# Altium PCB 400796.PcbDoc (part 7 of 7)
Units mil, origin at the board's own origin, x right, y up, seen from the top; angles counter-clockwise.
Board outline 2086.61 x 2086.61 mil, 6 copper layers (Top Layer, Mid Layer 1, Mid Layer 2, Mid Layer 3, Mid Layer 4, Bottom Layer), stack 58.818 mil thick; 313 components, 234 nets, 1244 pads, 2538 vias.
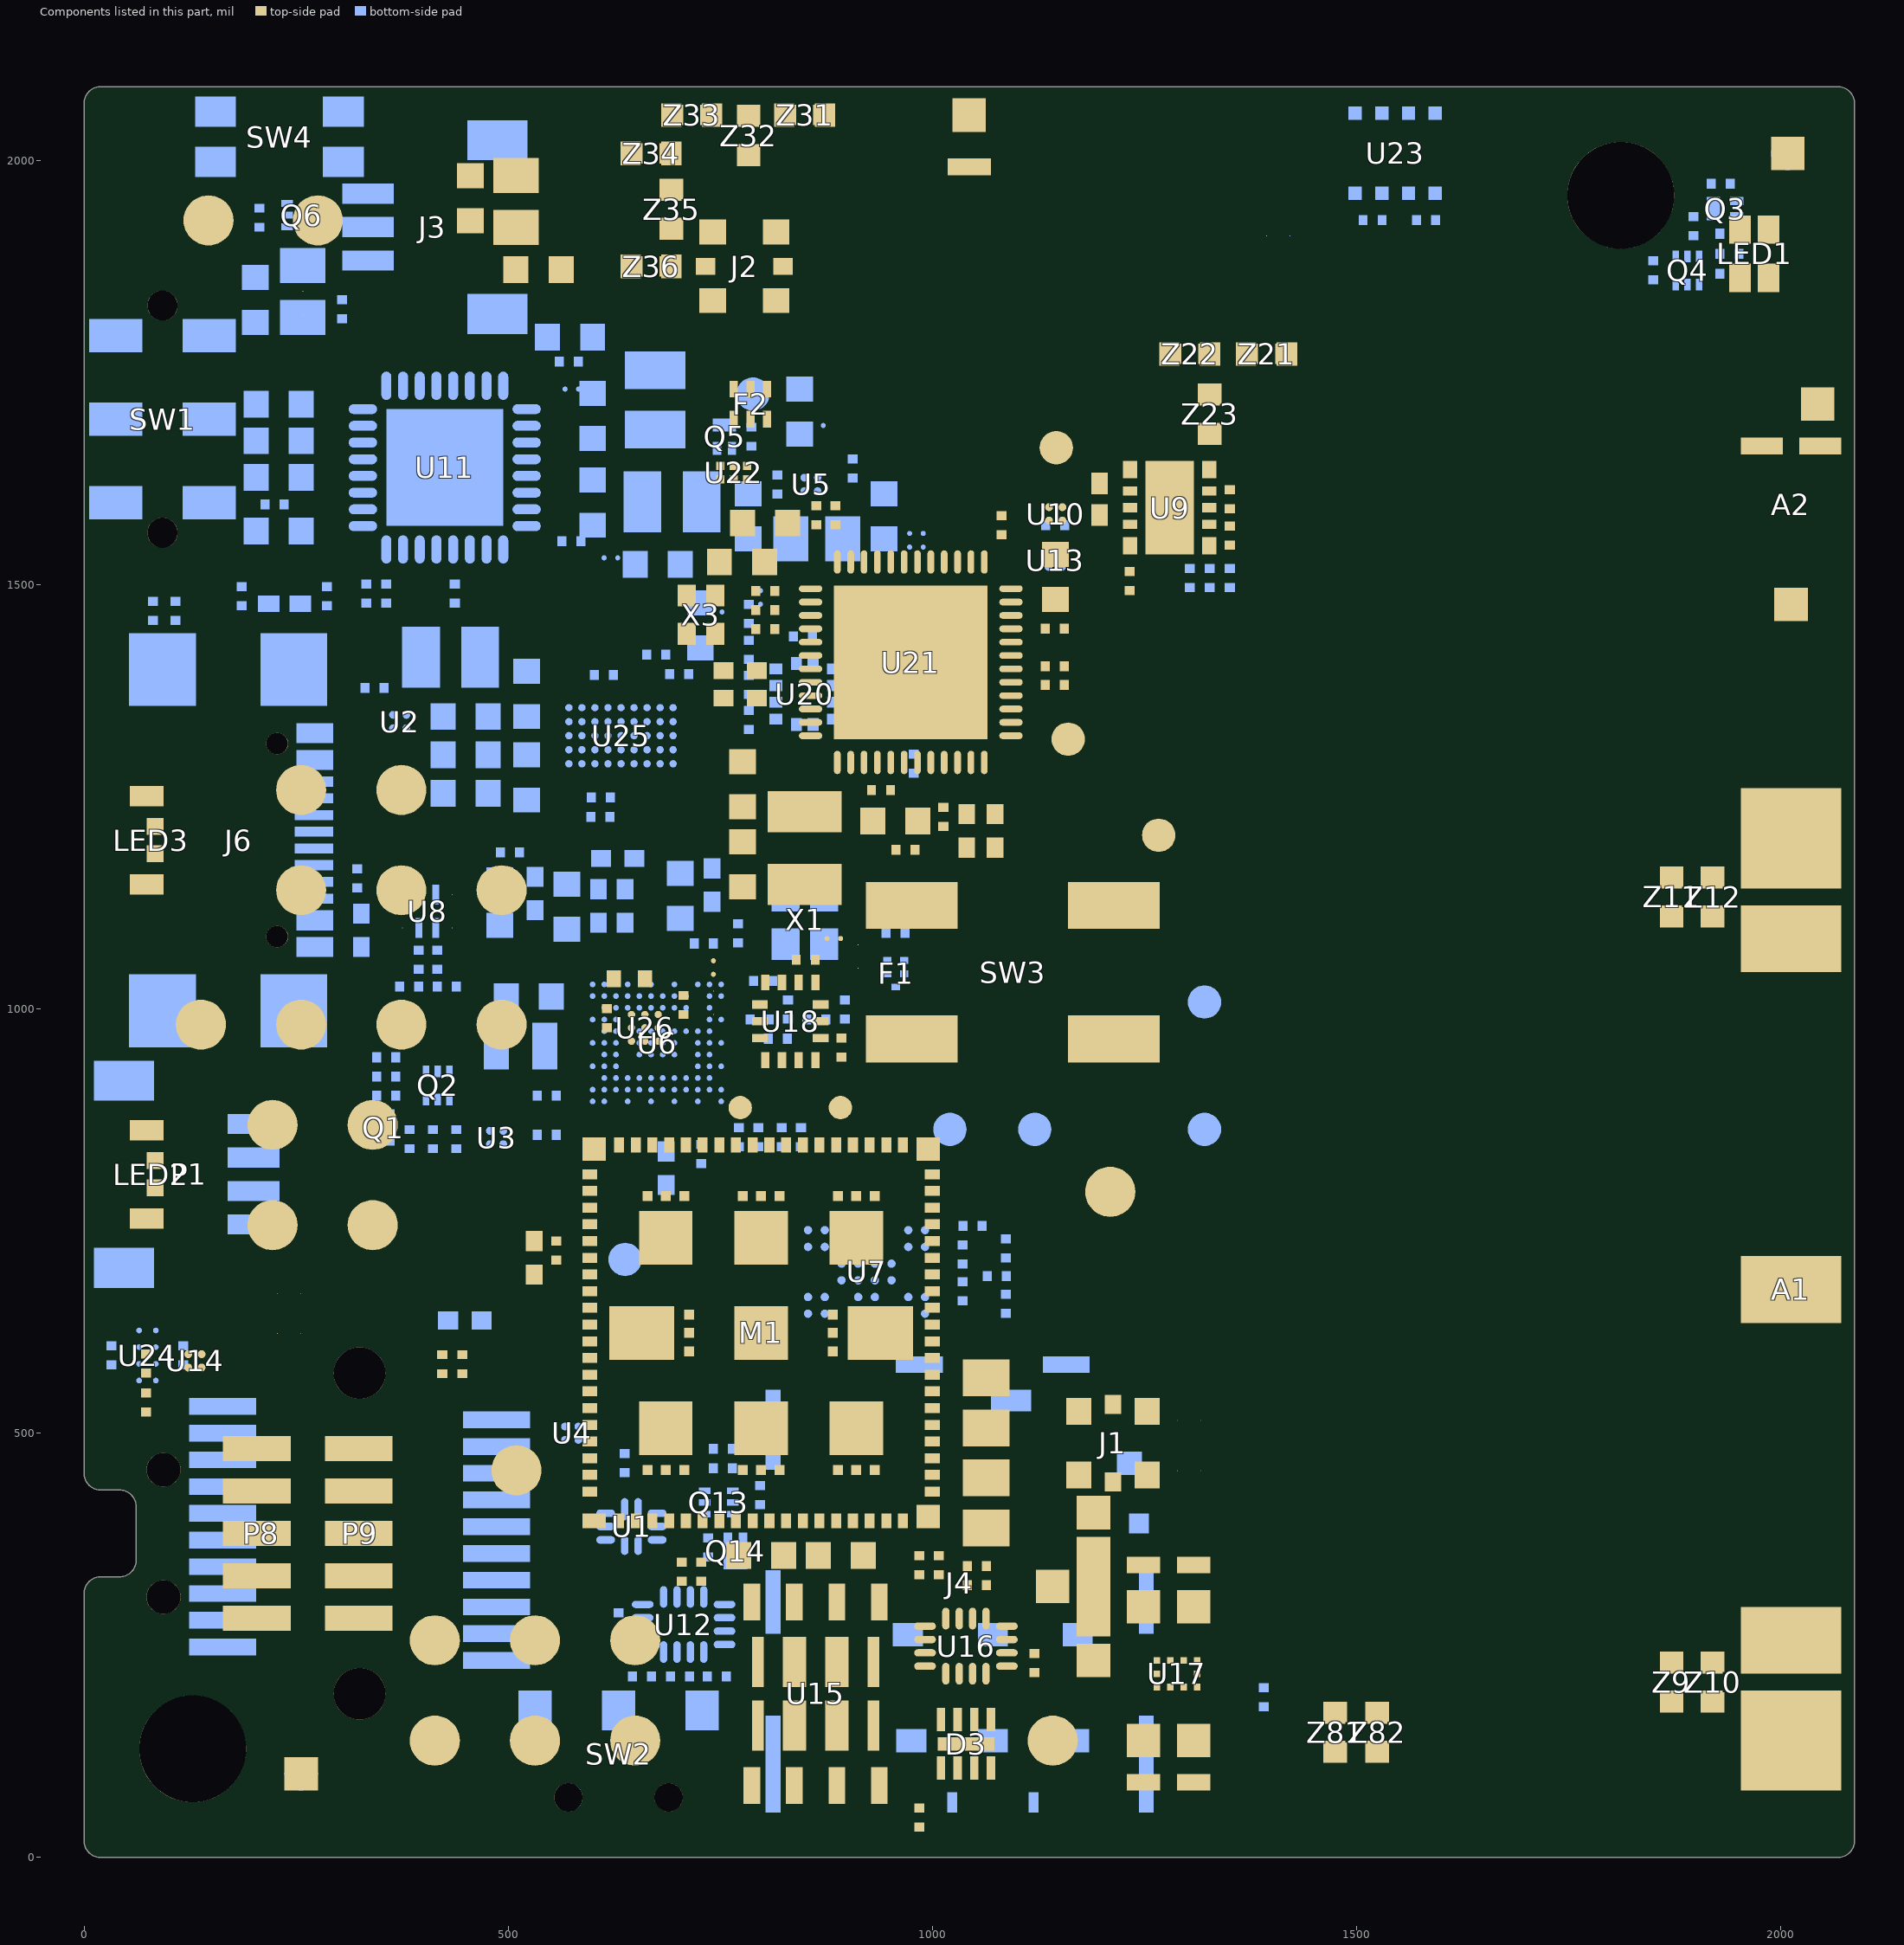
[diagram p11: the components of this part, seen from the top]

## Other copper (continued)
Mid Layer 4:
  rectangle net 3V3: 869.32,1539.19 958.71,1568.81
  region net 3V3_IND: 727.82,1509.17 727.82,1610.42 708.13,1610.42 708.13,1509.17
  region net GND: 641.73,1503.94 641.73,1582.68 577.5,1582.68 577.5,1503.94
  rectangle net GND: 534.45,1698.1 587.6,1750.94
  region net VDD_SENS: 828.29,1692.91 828.29,1662.4 859.25,1662.4 859.25,1692.91
  region net VDD_nRF53: 480.31,689.96 480.31,829.72 460.63,829.72 460.63,689.96
  region net 1V8_SW: 511.81,666.14 511.81,771.06 492.13,771.06 492.13,666.14
  region net 3V3: 365.16,578.74 365.16,448.82 384.84,448.82 384.84,578.74
  region net VBAT_nRF70: 332.49,1271.65 332.49,1239.17 449.8,1239.17 449.8,1271.65
  region net VOUT_BUCK3: 332.68,1313.98 332.68,1281.5 411.22,1281.5 411.22,1313.98
  region net NetC9_2: 224.41,1640.94 224.41,1567.12 314.96,1567.12 314.96,1640.94
  rectangle net VSYS_SW: 505.91,1230.81 572.31,1261.32
  rectangle net VSYS_SW: 505.91,1382.38 572.31,1412.89
  region net VBUS: 272.63,1525.59 199.8,1525.59 199.8,1494.09 272.63,1494.09
  rectangle net VBUS_CONN: 248.03,1270.67 312.01,1300.2
  region net VBUS: 288.64,1646.65 288.64,1696.85 224.41,1696.85 224.41,1646.65
  region net NetC9_2: 615.16,1608.27 615.16,1687.01 550.92,1687.01 550.92,1608.27
  region net 1V8_SW: 492.13,829.72 492.13,764.76 511.81,764.76 511.81,829.72
  region net VSYS_SW: 419.29,658.46 419.29,592.52 438.98,592.52 438.98,658.46
  rectangle net VOUT_BUCK3: 124.02,238.19 253.94,257.87
  region net VSYS_SW: 409.45,629.92 409.45,694.88 389.76,694.88 389.76,629.92
  rectangle net VDD_nRF53: 124.02,332.68 253.94,352.36
  region net VDD_nRF91: 525.59,525.59 446.85,525.59 446.85,505.91 525.59,505.91
  rectangle net 1V8_SW: 124.02,301.18 253.94,320.87
  rectangle net VBAT_nRF70: 124.02,269.68 253.94,289.37
  pour cut-out: 943.07,1025.61 943.07,1027.45 cw(c962.7,1027.45) 948.82,1041.34 ccw(c938.89,1051.26) 952.93,1051.26 952.93,1059.13 980.13,1059.13 980.13,1052.35 cw(c967.33,1052.35) 976.38,1043.31 ccw(c991.14,1028.55) 970.26,1028.55 970.26,1025.61
  pour cut-out: 875.24,973.81 cw(c875.24,987.41) 875.24,1001 933.22,1001 ccw(c933.22,1010.85) 943.07,1010.85 943.07,1025.61 cw(c956.67,1025.61) 970.26,1025.61 970.26,1010.85 cw(c933.22,1010.85) 933.23,973.81
  pour cut-out: 931.09,1202.94 cw(c931.09,1181.1) 952.93,1181.1 ccw(c966.53,1181.1) 952.93,1181.05 952.93,1059.13 ccw(c966.53,1059.13) 980.13,1059.13 980.13,1181.1 ccw(c966.53,1181.1) 980.13,1181.16 cw(c931.09,1181.1) 980.13,1181.1 980.13,1181.16 ccw(c931.09,1181.1) 931.09,1230.13 711.61,1230.13 ccw(c711.61,1216.54) 711.61,1202.94
  region net VBUS_CONN: 353.35,1148.62 288.39,1148.62 288.39,1101.38 317.91,1101.38 353.35,1136.81
  pour cut-out: 1446.85,1902.02 1663.39,1902.02 1663.39,2095.62 1446.85,2095.62
  region net VSYS_SW: 419.29,592.52 389.76,622.05 389.76,671.46 406.3,671.46 421.26,656.5 421.26,592.52
  region net VDD_nRF91: 472.63,525.59 482.13,525.59 529.39,572.85 588.58,572.85 588.58,557.09 537.4,505.91 472.64,505.91
Bottom Layer:
  rectangle net 1V8_SW: 688.77,1463.58 772.2,1493.11
  region net 3V3_IND: 727.82,1508.41 727.82,1574.35 708.13,1574.35 708.13,1508.41
  region net 3V3: 365.16,514.76 365.16,448.82 384.84,448.82 384.84,514.76
  region net VBAT_nRF70: 369.09,1309.06 330.71,1309.06 330.71,1238.19 369.09,1238.19
  rectangle net VOUT_BUCK3: 375,1238.19 419.49,1314.96
  region net VBUS: 272.63,1492.13 272.63,1511.81 199.8,1511.81 199.8,1492.13
  rectangle net VBUS_CONN: 284.45,1281.5 305.12,1305.12
  region net GND: 936.76,1058.11 936.76,1109.29 918.51,1109.29 918.51,1058.11
  region net VSYS_SW: 419.29,658.46 419.29,592.52 438.98,592.52 438.98,658.46
  rectangle net GND: 875.98,1017.18 913.39,1028.54
  rectangle net GND: 650.57,940.16 699.79,979.53
  region net SW3: 557.78,1305.3 560.84,1308.36 cw(c562.99,1306.21) 562.99,1309.25 570.35,1309.25 570.35,1302.95 561.52,1294.11 557.78,1297.85 557.78,1305.27
  region net VSYS_SW: 564.17,1276.77 cw(c570.07,1276.77) 565.9,1280.94 569.21,1284.25 569.21,1285.98 570.04,1285.98 570.83,1285.2 570.71,1285.08 570.71,1277.09
  region net SW0: 557.78,1338.4 560.84,1335.34 ccw(c562.99,1337.49) 562.99,1334.45 570.35,1334.45 570.35,1340.75 561.52,1349.59 557.78,1345.85 557.78,1338.43
  region net VSYS_SW: 564.17,1366.93 ccw(c570.07,1366.93) 565.9,1362.76 569.21,1359.45 569.21,1357.72 570.04,1357.72 570.83,1358.5 570.71,1358.62 570.71,1366.61
  region net VBAT_nRF70: 330.71,1298.23 330.71,1306.1 cw(c340.55,1306.1) 340.55,1315.94 ccw(c340.55,1323.78) 346.09,1318.24 354.39,1326.53 354.39,1298.23 342.52,1298.23
  region net VOUT_BUCK3: 408.46,1298.23 408.46,1306.1 ccw(c398.62,1306.1) 398.62,1315.95 cw(c398.62,1323.78) 393.08,1318.24 384.79,1326.53 384.79,1298.23 396.65,1298.23
  region net VOUT_BUCK3: 375,1330.71 cw(c379.92,1330.71) 379.92,1335.63 cw(c379.92,1330.88) 383.28,1334.24 383.86,1333.66 cw(c350.59,1300.39) 397.64,1300.39 397.64,1291.34 376.97,1291.34 cw(c381.71,1296.09) 375,1296.09 375,1315.95
  region net VBAT_nRF70: 369.09,1330.71 ccw(c364.17,1330.71) 364.17,1335.63 ccw(c364.17,1330.88) 360.81,1334.24 360.24,1333.66 ccw(c393.51,1300.39) 346.46,1300.39 346.46,1291.34 367.13,1291.34 ccw(c362.38,1296.09) 369.09,1296.09 369.09,1315.95
  region net VDD_nRF53: 483.27,840.55 ccw(c478.35,840.55) 478.35,845.47 ccw(c478.35,840.72) 474.99,844.08 474.41,843.5 ccw(c507.68,810.24) 460.63,810.24 460.63,794.29 480.31,794.29 480.31,798.81 cw(c483.68,798.81) 481.3,801.18 ccw(c476.55,805.93) 483.27,805.93 483.27,825.79
  region net 1V8_SW: 489.17,840.55 cw(c494.09,840.55) 494.09,845.47 cw(c494.09,840.72) 497.45,844.08 498.03,843.5 cw(c464.76,810.24) 511.81,810.24 511.81,794.29 492.13,794.29 492.13,798.81 ccw(c488.77,798.81) 491.14,801.18 cw(c495.89,805.93) 489.17,805.93 489.17,825.79
  region net VDD_nRF91_RES: 566.93,497.05 cw(c566.93,492.13) 571.85,492.13 cw(c567.1,492.13) 570.46,488.77 569.88,488.19 cw(c536.61,521.46) 536.61,474.41 520.67,474.41 520.67,494.09 525.18,494.09 ccw(c525.18,497.45) 527.56,495.08 cw(c532.31,490.33) 532.31,497.05 552.17,497.05
  region net VDD_nRF91: 566.93,502.95 ccw(c566.93,507.87) 571.85,507.87 ccw(c567.1,507.87) 570.46,511.23 569.88,511.81 ccw(c536.61,478.54) 536.61,525.59 520.67,525.59 520.67,505.91 525.18,505.91 cw(c525.18,502.55) 527.56,504.92 ccw(c532.31,509.67) 532.31,502.95 552.17,502.95
  region net VSYS: 119.96,1773.62 119.96,1835.53 200.74,1835.53 284.33,1835.53 284.33,1794.19 199.5,1794.19 178.93,1773.62
  region net 3V3: 882.85,1570.74 882.85,1537.09 976.3,1537.09 976.3,1570.75 884.58,1570.75
  region net VBUS: 295.22,1660.54 302.22,1653.54 337.7,1653.54 341.07,1650.17 341.07,1644.27 338.53,1641.73 294.91,1641.73 287.91,1648.73 229.5,1648.73 229.5,1685.15 270.62,1685.15
  pour cut-out: 820.87,1417.32 820.87,1348.43 907.48,1348.43 907.48,1417.32 908.46,1417.32
  region net VBUS: 230.31,1487.2 235.24,1492.13 245.08,1492.13 245.08,1511.81 190.23,1511.81 180.12,1501.7 180.12,1492.13 199.8,1492.13 204.72,1487.2 204.72,1483.27 230.31,1483.27
  pour cut-out: 461.61,1283.46 437.99,1283.46 437.99,1360.24 461.61,1360.24
  region net VBUS_CONN: 339.5,1122.96 381.89,1122.96 381.89,1151.79 330.92,1151.79 295.28,1116.14 288.39,1116.14 288.39,1092.52 309.06,1092.52
  region net VBAT: 330.71,1602.36 310.04,1602.36 275.59,1567.91 254.92,1547.24 237.21,1547.24 237.21,1578.74 259.84,1578.74 263.78,1582.68 295.28,1614.17 330.71,1614.17
  pour cut-out: 498.03,1710.63 352.36,1710.63 352.36,1564.96 498.03,1564.96
  region net PVSS1: 615.16,1797.24 584.65,1797.24 584.65,1768.64 563.35,1747.35 543.31,1747.35 543.31,1701.77 534.45,1692.91 521.65,1692.91 521.65,1681.1 542.32,1681.1 571.85,1710.63 615.16,1710.63
  region net 1V8_IND: 684.76,1818.9 653.27,1850.39 570.87,1850.39 531.5,1850.39 531.5,1819.88 531.5,1794.17 561.02,1794.17 561.02,1801.57 578.35,1818.9
  region net NetC9_2: 562.99,1653.54 583.66,1674.21 583.66,1687.01 615.16,1687.01 615.16,1608.27 583.66,1608.27 583.66,1621.06 562.99,1641.73
  region net 1V8_IND: 620.94,1818.91 636.81,1803.04 636.81,1729.33 709.06,1729.33 709.06,1794.61 664.11,1839.55 620.94,1839.55
  pour cut-out: 719.05,1729.33 719.05,1633.27 636.81,1633.27 636.81,1729.33
  region net 3V3_IND: 750.7,1531.05 841.03,1531.05 849.19,1539.22 849.19,1572.37 843.64,1577.92 753.89,1577.92 750,1581.81 750,1633.27 704.72,1633.27 704.72,1561.02 687.99,1544.29 687.99,1507.87 727.52,1507.87
  region net PVSS2: 521.65,1614.17 543.31,1614.17 572.83,1584.65 615.16,1584.65 615.16,1569.88 645.67,1539.37 680.12,1539.37 680.12,1507.87 594.49,1507.87 580.71,1521.65 580.71,1556.1 534.45,1602.36 521.65,1602.36
  pour cut-out: 681.1,1528.9 681.1,1497.84 548.76,1497.84 548.76,1528.9
  pour cut-out: 134.84,1655.51 134.84,1621.66
  region net NetC9_2: 283.11,1641.86 291.11,1633.86 338.78,1633.86 342.01,1630.63 342.01,1624.79 339.26,1622.05 289.86,1622.05 273.26,1605.44 229.5,1605.44 229.5,1641.86
  pour cut-out: 1446.85,1902.02 1663.39,1902.02 1663.39,2095.62 1446.85,2095.62
  region net 1V8_SW: 492.13,794.29 492.13,771.65 499.02,764.76 511.81,764.76 511.81,795.28 492.13,795.28
  region net VDD_nRF53: 460.63,794.29 460.63,771.65 467.52,764.76 480.31,764.76 480.31,795.28 460.63,795.28
  pour cut-out: 781.48,1038.58 781.48,1161.61 915.97,1161.61 915.97,1038.58
  pour cut-out: 686.99,1030.71 686.99,973.62 756.87,973.62 756.87,1030.71
  pour cut-out: 821.64,1026.77 821.64,1020.67 840.53,1020.67 840.53,998.23 754.9,998.23 754.9,1026.77
Multi-Layer:
  pour cut-out: 1520.8,1795.67 1520.8,1747.64 1303.08,1747.64 1303.08,1795.67
  pour cut-out: 1303.08,1748.22 1303.08,1653.89 1351.19,1653.89 1351.19,1748.23
  pour cut-out: 668.1,2029.72 668.1,1852.27 716.2,1852.27 716.2,2029.73
  pour cut-out: 885.81,2077.16 885.81,2029.13 668.1,2029.13 668.1,2077.16
  pour cut-out: 885.83,2086.61 1200.79,2086.61 1200.79,1771.65 885.83,1771.65
  pour cut-out: 1440.95,9.84 1440.95,1850.39 2133.86,1850.39 2133.86,9.84

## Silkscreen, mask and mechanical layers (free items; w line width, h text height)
Top Overlay:
  region: 1529.74,2063.12 ccw(c1519.78,1964.04) 1529.74,1864.96 1529.74,1894.84 cw(c1519.78,1964.04) 1529.74,2033.25
  region: 1620.76,1978.98 cw(c1689.06,1964.04) 1699.02,2033.25 1699.02,2063.12 ccw(c1689.06,1964.04) 1699.02,1864.96 1699.02,1894.84 cw(c1689.06,1964.04) 1620.76,1949.11 1689.06,1949.11 1689.06,1978.98
  text "'.PCBNumber'" at 1727.95,2030.7 h70
  text "BUTTON 2" at 53.15,2005.91 h70.87
  text "LED1" at 2011.76,1967.66 h70.87 r270
  text "ON" at 5.34,1872.04 h70.87 r270
  text "POWER" at 112.21,1872.04 h70.87 r270
  text ".PCBRevision" at 1727.93,1858.84 h40
  text "OFF" at 5.34,1655.51 h70.87 r270
  text "For evaluation only; / not FCC approved for resale." at 226.53,1423.32 h55
  text "CHARGE LED" at 102.72,1332.98 h70.87 r270
  text "LED2" at 105.55,872.74 h70.87 r270
  text "BUTTON 1" at 917.32,860.86 h70.87
  text "SWD" at 570.87,54.13 h55.12
  text "nRF53" at 486.22,5.91 h55.12
  text "nRF91" at 627.95,5.91 h55.12
Board Outline:
  lines w5.91: 2066.93,0 ccw(c2066.93,19.69) 2086.61,19.69 ; 2066.93,0 ccw(c2066.93,19.69) 2086.61,19.69 ; 2066.93,0 19.68,0 cw(c19.68,19.69) 0,19.69 0,311.02 cw(c19.69,311.02) 19.69,330.71 41.73,330.71 ccw(c41.73,350.39) 61.42,350.39 61.42,413.38 ccw(c41.73,413.38) 41.73,433.07 19.68,433.07 cw(c19.68,452.75) 0,452.75 0,2066.93 cw(c19.68,2066.93) 19.68,2086.61 2066.93,2086.61 cw(c2066.93,2066.94) 2086.61,2066.94 2086.61,19.69
Board Other:
  drawing of 2516 lines, arcs and shapes, not listed
Dimension:
  drawing of 463 lines, arcs and shapes, not listed
Top Impedance Info:
  lines w11.42: 711.61,1216.54 689.05,1216.54 cw(c689.05,1261.74) 643.84,1261.74 643.84,1577.85 cw(c690.01,1577.85) 690.01,1624.02 750,1624.02 ; 765.75,1641.02 765.75,1698.82 ; 782.48,1624.02 899.61,1624.02 cw(c899.61,1588.58) 935.04,1588.58 935.04,1526.57 ; 785.43,1730.31 785.43,1747.09 cw(c827.73,1747.09) 797.82,1776.99 798.25,1777.42 cw(c818.88,1756.78) 818.88,1785.97 ccw(c818.88,1809.4) 835.45,1792.83 836.78,1794.16 ccw(c803.96,1826.99) 850.38,1826.99 850.38,1858.31 ccw(c833.59,1858.31) 845.46,1870.18 ccw(c833.99,1858.71) 833.99,1874.93 823.92,1874.93 ; 806.1,1694.88 918.28,1694.88 cw(c918.28,1646.63) 966.54,1646.63 966.54,1526.57
  lines w25.12: 965.08,869.54 965.08,866.12 cw(c1001.4,866.12) 975.72,891.81 cw(c998.71,868.82) 998.71,901.33 1261.27,901.33 ccw(c1261.27,990.9) 1324.61,927.57 ccw(c1262.78,989.39) 1350.22,989.39 1350.22,1245.98 ccw(c1250.22,1245.98) 1320.93,1316.69 1261.4,1376.22 cw(c1332.11,1446.93) 1232.11,1446.93 1232.11,1487.4 ; 1026,706.54 1078.19,706.54 cw(c1078.19,606.54) 1148.9,677.25 1183.3,642.85 cw(c1112.59,572.14) 1212.59,572.14 1212.59,533.75 ; 1203.3,418.89 ccw(c1180.85,441.34) 1212.6,441.34 ; 1232.78,1520.67 1232.78,1545.53 ; 1326.28,1635.57 1326.28,1676.28 1326.77,1676.77 ; 1326.77,1724.8 1326.77,1771.26 1327.17,1771.65 1369.68,1771.65
  text "50 ohm impedance, CPW" at 450.79,1143.7 h70
  text "50 ohm impedance, CPW" at 840.92,768.61 h70
Bottom Impedance Info:
  lines w3.27: 232.28,1183.07 cw(c246.54,1168.81) 246.54,1188.98 270.87,1188.98 cw(c284.64,1175.2) 284.64,1194.68 304.64,1194.68 ccw(c304.64,1220.78) 323.09,1202.32 cw(c345.52,1179.9) 345.52,1211.61 382.22,1211.61 cw(c382.22,1192.57) 395.69,1206.04 cw(c386.99,1197.34) 399.29,1197.34 399.29,1155.2 cw(c356.17,1155.2) 386.66,1124.72 375.47,1113.52 cw(c365.16,1123.83) 365.16,1109.25 cw(c365.16,1094.21) 375.8,1104.85 397.35,1083.29 cw(c390.19,1076.13) 400.32,1076.13 cw(c397.26,1076.13) 399.42,1073.96 394.47,1069.01 ; 232.28,1214.57 ccw(c246.54,1228.82) 246.54,1208.66 270.87,1208.66 ccw(c284.64,1222.44) 284.64,1202.96 304.64,1202.96 ccw(c304.64,1220.78) 317.24,1208.18 cw(c345.52,1179.9) 345.52,1219.89 382.22,1219.89 cw(c382.22,1192.57) 401.54,1211.89 cw(c386.99,1197.34) 407.56,1197.34 407.56,1155.2 ccw(c441.94,1155.2) 417.63,1130.9 434.62,1113.91 ccw(c445.87,1125.16) 445.87,1109.25 ccw(c445.87,1094.09) 435.15,1104.81 414.17,1083.84 ; 416.21,1069.01 411.31,1073.92 cw(c412.81,1075.42) 410.69,1075.42 cw(c422.59,1075.42) 414.16,1083.83 ; 599.39,1028.74 595.62,1032.51 ccw(c578.19,1015.08) 578.19,1039.73 485.6,1039.73 ccw(c485.6,1023.39) 474.06,1034.95 ; 613.17,1028.74 605.02,1036.89 ccw(c578.19,1010.06) 578.19,1048 485.6,1048 ccw(c485.6,1023.39) 468.2,1040.79 465.56,1038.15 ccw(c479.66,1024.05) 459.72,1024.05 459.72,1011.69 cw(c455.9,1011.69) 458.6,1008.98 cw(c429.92,1037.66) 437.22,997.77 cw(c429.92,1037.66) 429.92,997.11 421.82,997.11 cw(c421.82,1005.47) 415.91,999.56 413.86,1001.6 cw(c424.45,1012.19) 409.48,1012.19 cw(c427.47,1012.19) 414.75,1024.91 416.21,1026.38 416.21,1046.57 ; 394.47,1046.57 394.47,1046.57 ; 394.47,1046.57 394.47,1026.38 395.93,1024.91 cw(c383.21,1012.19) 401.2,1012.19 ccw(c424.45,1012.19) 408.01,995.75 410.06,993.71 ccw(c421.82,1005.47) 421.82,988.83 431.48,988.83 ccw(c431.48,1033.89) 438.1,989.32 ccw(c431.48,1033.89) 463.34,1002.03 464.45,1003.13 ccw(c455.9,1011.69) 467.99,1011.69 467.99,1024.05 cw(c479.66,1024.05) 471.4,1032.29 ; 414.17,1083.84 ccw(c422.59,1075.42) 414.16,1083.83 ; 414.16,1083.83 414.17,1083.84 ; 416.21,1046.57 416.21,1046.57 ; 471.41,1032.3 ccw(c479.66,1024.05) 471.4,1032.29 ; 471.4,1032.29 471.41,1032.3 ; 471.41,1032.3 474.05,1034.94 ; 474.06,1034.95 ccw(c485.6,1023.39) 474.05,1034.94 ; 474.05,1034.94 474.06,1034.95
  lines w11.42: 711.61,1216.54 931.09,1216.54 cw(c931.09,1181.1) 966.53,1181.1 966.53,1057.11 ; 875.24,987.41 933.22,987.41 ccw(c933.22,1010.85) 956.67,1010.85 956.67,1025.61
  text "50 ohm impedance, CPW" at 743.11,1238.19 h70
  text "90 ohm differential impedance" at 60.67,933.28 h70
Mechanical 31:
  lines w5.91: -1423.45,659.28 -39.37,659.28 ; -1423.45,950.95 -39.37,950.95 ; -1423.45,1000.95 -39.37,1000.95 ; -1423.45,1085.67 -39.37,1085.67 ; -1417.89,152.34 -39.37,152.34 ; -1417.89,609.28 -39.37,609.28
Mechanical 32:
  lines w5.91: -1575.08,155.5 -59.06,155.5 -59.06,608.28 -1575.08,608.28 ; -1511.88,859.96 -59.06,859.96 -59.06,1226.63 -1511.88,1226.63 ; -1335.73,1524.62 -78.74,1524.62 ; -1335.04,1466.28 -78.74,1466.28 ; -1334.35,1938.51 -78.74,1938.51 ; -1334.35,1977.39 -78.74,1977.39 ; -1255.87,1564.89 -78.74,1564.89 -78.74,1899.62 -1255.87,1899.62

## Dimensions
825.79,2281.5 to 166.34,2281.5 on Dimension
166.34,2281.5 to 166.34,2832.68 on Dimension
